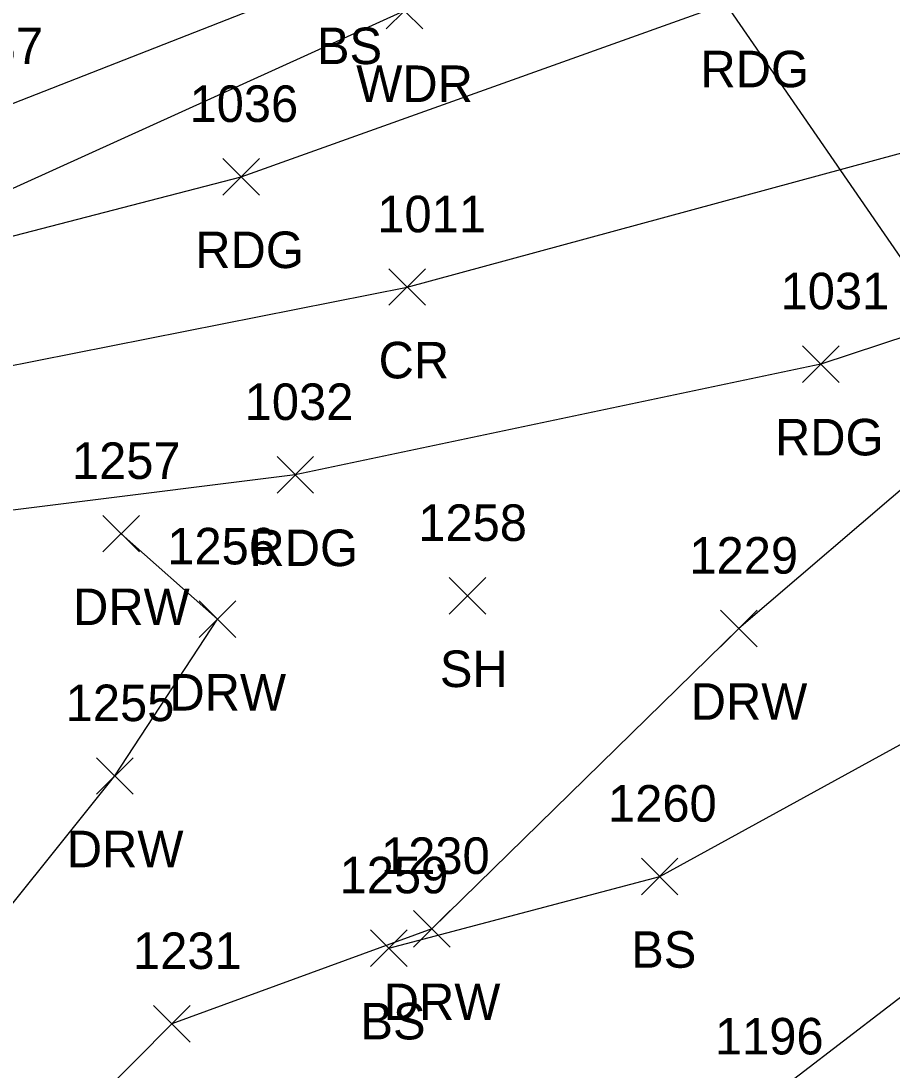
# Model space of a CAD drawing. Extents: x 1621633 to 1624015, y 417863 to 420979.
# Drawn here: x 1622009 to 1622056.7, y 418067.9 to 418125.3 of the extents above; entities that cross this region are included whole.
import ezdxf

# ---------------------------------------------------------------- set-up
doc = ezdxf.new("R2010")
doc.units = 0
for name, color, linetype in [('DCP', 7, 'Continuous'), ('L_A', 7, 'Continuous'), ('L_I', 7, 'Continuous'), ('L_TIC', 7, 'Continuous'), ('LAWA', 7, 'Continuous'), ('LELB', 7, 'Continuous'), ('P_A', 7, 'Continuous'), ('P_I', 7, 'Continuous'), ('P_TIC', 7, 'Continuous'), ('PEU', 7, 'Continuous'), ('PRC', 7, 'Continuous'), ('R_A', 7, 'Continuous'), ('R_I', 7, 'Continuous'), ('R_TIC', 7, 'Continuous'), ('RDW', 7, 'Continuous')]:
    doc.layers.add(name, color=color, linetype=linetype)

msp = doc.modelspace()

# ---------------------------------------------------------------- linework, layer by layer
at = {"layer": 'DCP'}
msp.add_lwpolyline([(1622041.571, 418135.015), (1622064.541, 418101.676)], dxfattribs=at)
at = {"layer": 'L_TIC'}
for points in [[(1622029.014, 418124.886), (1622031.014, 418126.886)], [(1622031.014, 418124.886), (1622029.014, 418126.886)], [(1622032.466, 418092.854), (1622034.466, 418094.854)], [(1622034.466, 418092.854), (1622032.466, 418094.854)], [(1622042.987, 418077.486), (1622044.987, 418079.486)], [(1622044.987, 418077.486), (1622042.987, 418079.486)], [(1622028.164, 418073.561), (1622030.164, 418075.561)], [(1622030.164, 418073.561), (1622028.164, 418075.561)]]:
    msp.add_lwpolyline(points, dxfattribs=at)
at = {"layer": 'LAWA'}
for points in [[(1622320.208, 418157.076), (1622282.224, 418156.146), (1622251.71, 418155.079), (1622223.599, 418155.089), (1622209.107, 418155.31), (1622180.877, 418152.893), (1622152.121, 418150.865), (1622117.366, 418144.737), (1622094.144, 418141.694), (1622062.956, 418134.278), (1622030.014, 418125.886), (1622002.089, 418113.22), (1622001.944, 418118.19), (1622004.405, 418142.605), (1621992.552, 418166.206), (1621982.92, 418190.962), (1621974.219, 418213.574), (1621987.215, 418225.085), (1622016.711, 418238.58), (1622052.182, 418242.586)], [(1622320.95, 418130.743), (1622294.184, 418128.87), (1622284.857, 418124.812), (1622280.855, 418118.535), (1622268.545, 418119.809), (1622252.021, 418123.74), (1622232.124, 418123.259), (1622206.962, 418121.212), (1622178.234, 418118.308), (1622148.867, 418114.963), (1622127.557, 418112.544), (1622101.307, 418110.446), (1622091.62, 418108.262), (1622075.892, 418086.213), (1622049.191, 418065.738), (1622027.926, 418059.192), (1622009.751, 418042.713)]]:
    msp.add_lwpolyline(points, dxfattribs=at)
at = {"layer": 'LELB'}
for points in [[(1622006.415, 418119.96), (1622026.784, 418127.961), (1622037.161, 418131.419)], [(1622029.164, 418074.561), (1622043.987, 418078.486), (1622059.4, 418086.928), (1622068.241, 418092.913), (1622073.97, 418100.794)]]:
    msp.add_lwpolyline(points, dxfattribs=at)
at = {"layer": 'P_TIC'}
for points in [[(1622020.077, 418115.794), (1622022.077, 418117.794)], [(1622022.077, 418115.794), (1622020.077, 418117.794)], [(1622029.167, 418109.754), (1622031.167, 418111.754)], [(1622031.167, 418109.754), (1622029.167, 418111.754)], [(1622051.808, 418105.537), (1622053.808, 418107.537)], [(1622053.808, 418105.537), (1622051.808, 418107.537)], [(1622023.042, 418099.476), (1622025.042, 418101.476)], [(1622025.042, 418099.476), (1622023.042, 418101.476)]]:
    msp.add_lwpolyline(points, dxfattribs=at)
at = {"layer": 'PEU'}
msp.add_lwpolyline([(1622194.167, 418133.578), (1622165.782, 418130.649), (1622135.81, 418126.422), (1622106.702, 418121.829), (1622082.092, 418116.179), (1622052.808, 418106.537), (1622024.042, 418100.476), (1621997.915, 418097.203), (1621996.78, 418104.27), (1621996.214, 418110.35), (1622021.077, 418116.794), (1622048.73, 418126.692), (1622081.221, 418135.215), (1622108.123, 418139.761), (1622139.716, 418144.656), (1622170.966, 418148.681), (1622202.204, 418150.62)], dxfattribs=at)
at = {"layer": 'PRC'}
msp.add_lwpolyline([(1621997.748, 418104.333), (1622030.167, 418110.754), (1622061.28, 418119.206), (1622091.298, 418126.36), (1622119.867, 418131.333), (1622150.166, 418136.531), (1622182.15, 418139.317), (1622212.387, 418141.944), (1622242.915, 418142.528), (1622274.163, 418143.677), (1622303.741, 418144.568), (1622320.756, 418144.646)], dxfattribs=at)
at = {"layer": 'R_TIC'}
for points in [[(1622013.506, 418096.249), (1622015.506, 418098.249)], [(1622015.506, 418096.249), (1622013.506, 418098.249)], [(1622018.779, 418091.569), (1622020.779, 418093.569)], [(1622020.779, 418091.569), (1622018.779, 418093.569)], [(1622047.314, 418091.064), (1622049.314, 418093.064)], [(1622049.314, 418091.064), (1622047.314, 418093.064)], [(1622013.164, 418082.988), (1622015.164, 418084.988)], [(1622015.164, 418082.988), (1622013.164, 418084.988)], [(1622030.513, 418074.622), (1622032.513, 418076.622)], [(1622032.513, 418074.622), (1622030.513, 418076.622)], [(1622016.283, 418069.416), (1622018.283, 418071.416)], [(1622018.283, 418069.416), (1622016.283, 418071.416)]]:
    msp.add_lwpolyline(points, dxfattribs=at)
at = {"layer": 'RDW'}
for points in [[(1622068.286, 418109.151), (1622048.314, 418092.064), (1622031.513, 418075.622), (1622017.283, 418070.416), (1621999.079, 418052.056), (1621978.461, 418032.933), (1621951.05, 418013.179), (1621921.756, 418000.239), (1621894.363, 417990.232), (1621865.95, 417979.751)], [(1621869.66, 417990.005), (1621898.189, 417999.842), (1621925.17, 418010.412), (1621952.262, 418024.445), (1621976.225, 418041.199), (1621996.59, 418062.054), (1622014.164, 418083.988), (1622019.779, 418092.569), (1622014.506, 418097.249)]]:
    msp.add_lwpolyline(points, dxfattribs=at)

# ---------------------------------------------------------------- texts
at = {"layer": 'L_A'}
for s, p in [('BS', (1622025.225, 418122.961)), ('WDR', (1622027.376, 418120.886)), ('SH', (1622031.954, 418088.854)), ('BS', (1622042.428, 418073.486)), ('BS', (1622027.605, 418069.561))]:
    msp.add_text(s, height=2, dxfattribs=at).set_placement(p)
at = {"layer": 'L_I'}
for s, p in [('1137', (1622004.289, 418122.96)), ('1258', (1622030.773, 418096.854)), ('1260', (1622041.16, 418081.486)), ('1259', (1622026.463, 418077.561)), ('1196', (1622047.01, 418068.738))]:
    msp.add_text(s, height=2, dxfattribs=at).set_placement(p)
at = {"layer": 'P_A'}
for s, p in [('RDG', (1622046.218, 418121.692)), ('RDG', (1622018.565, 418111.794)), ('CR', (1622028.6, 418105.754)), ('RDG', (1622050.296, 418101.537)), ('RDG', (1622021.531, 418095.476))]:
    msp.add_text(s, height=2, dxfattribs=at).set_placement(p)
at = {"layer": 'P_I'}
for s, p in [('1036', (1622018.25, 418119.794)), ('1011', (1622028.529, 418113.754)), ('1031', (1622050.603, 418109.537)), ('1032', (1622021.271, 418103.476))]:
    msp.add_text(s, height=2, dxfattribs=at).set_placement(p)
at = {"layer": 'R_A'}
for p in [(1622011.876, 418092.249), (1622017.149, 418087.569), (1622045.684, 418087.064), (1622011.534, 418078.988), (1622028.883, 418070.622)]:
    msp.add_text('DRW', height=2, dxfattribs=at).set_placement(p)
at = {"layer": 'R_I'}
for s, p in [('1257', (1622011.813, 418100.249)), ('1256', (1622017.031, 418095.569)), ('1229', (1622045.613, 418095.064)), ('1255', (1622011.471, 418086.988)), ('1230', (1622028.734, 418078.622)), ('1231', (1622015.157, 418073.416))]:
    msp.add_text(s, height=2, dxfattribs=at).set_placement(p)

doc.saveas('drawing.dxf')
